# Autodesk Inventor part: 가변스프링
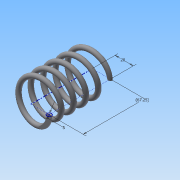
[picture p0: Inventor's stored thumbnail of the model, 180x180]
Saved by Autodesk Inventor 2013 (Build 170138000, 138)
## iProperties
Created: 2018-08
Part Number: 가변스프링
Material: 일반
Document SubType Name: Modeling
Designer: user
Density: 1 g/cm^3
Mass: 12.1667 g
Surface Area: 98.6263 cm^2
Volume: 12.1667 cm^3
Author: user
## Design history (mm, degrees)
sketch "스케치1"
  geometry: L1 (0, 0)-(20, 0); L2 (20, 0)-(20, 67.25); L3 (20, 67.25)-(0, 67.25); L4 (0, 67.25)-(0, 0); C1 r 2.5 at (20, 0)
  constraints: 8 end point, 2 parallel, 1 centre point, 1 coincident, 1 horizontal, 1 perpendicular
  dimensions: "d0" = 20 distance of L2.end L3.end; "d2" = 67.25 distance of L1.end L2.end (derived); "d3" = 5 diameter of C1
feature "코일1" pitch "d4" = 10; turns "d6" = 5; dims "d5" = 67.25 (= d2), "d7" = 0, angle "d8" = 90 deg, angle "d9" = 90 deg, "d10" = 0, "d11" = 0
sketch "스케치2"
  geometry: L1 (-22.5, 0)-(-17.5, 0) reference; L2 (-22.5, 0)-(-17.5, 0) reference; 1 further point
  constraints: 2 horizontal alignment
extrude "돌출1" cut sketch "스케치2" distance "d12" = 10; taper "d13" = 0 deg
node "작업 평면1"
sketch "스케치3"
  geometry: L1 (22.5, 0)-(17.5, 0) reference; 1 further point
  constraints: 1 horizontal alignment
extrude "돌출2" cut sketch "스케치3" distance "d14" = 10; taper "d15" = 0 deg
node "솔리드1"
node "절단 모서리 투영1"
node "절단 모서리 투영2"
node "절단 모서리 투영3"
